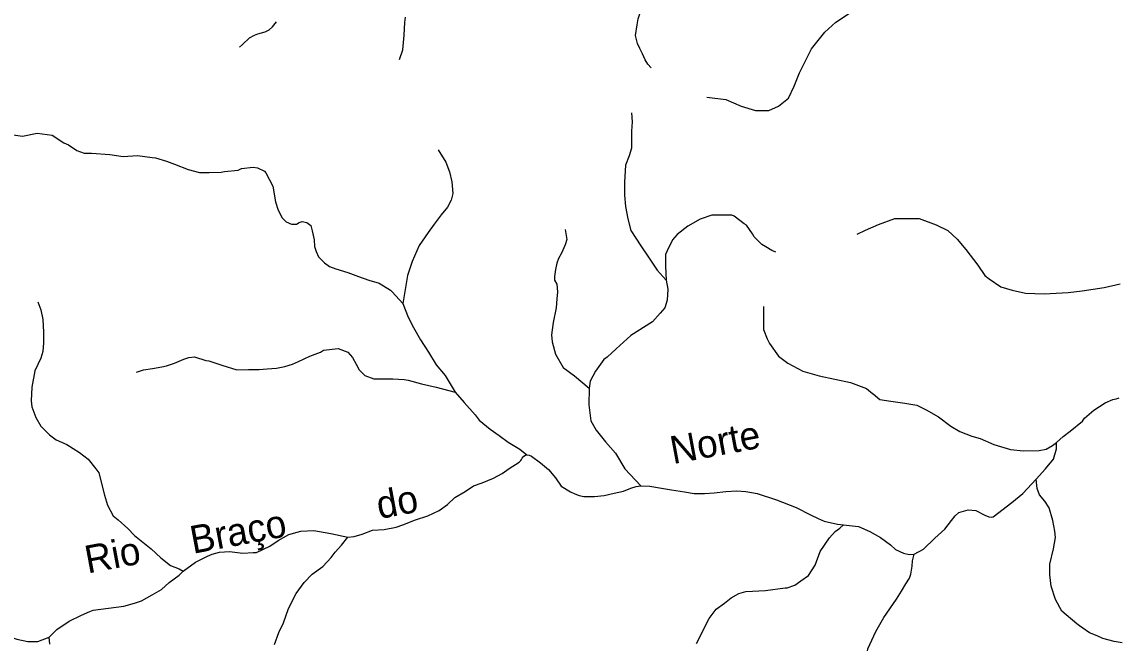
# Model space of a CAD drawing. Extents: x 436.3 to 500.4, y 8231 to 8286.4.
# Drawn here: x 465.65 to 473.55, y 8253.25 to 8257.73 of the extents above; entities that cross this region are included whole.
import ezdxf
from ezdxf.enums import TextEntityAlignment as Align

# ---------------------------------------------------------------- set-up
doc = ezdxf.new("R2010")
doc.units = 0
doc.header["$LTSCALE"] = 0.08
doc.linetypes.add('LONG_DASHED', pattern=[7.5, 6, -1.5])
doc.layers.add('61', color=7, linetype='Continuous')
doc.layers.add('9', color=7, linetype='LONG_DASHED', lineweight=25)

msp = doc.modelspace()

# ---------------------------------------------------------------- linework, layer by layer
at = {"layer": '9'}
for points in [[(470.1875, 8257.4013), (470.1642, 8257.4285), (470.1446, 8257.4597), (470.1251, 8257.5025), (470.1055, 8257.5413), (470.09, 8257.5764), (470.0743, 8257.6348), (470.086, 8257.7126), (470.0937, 8257.7554), (470.1248, 8257.8489), (470.1793, 8257.9541), (470.2804, 8258.0726), (470.335, 8258.1505), (470.3622, 8258.2011), (470.3856, 8258.2751), (470.3939, 8258.3915)], [(470.5903, 8257.1891), (470.7255, 8257.1733), (470.8369, 8257.1257), (470.9403, 8257.0941), (471.0358, 8257.0942), (471.1074, 8257.126), (471.1789, 8257.1818), (471.2186, 8257.2692), (471.2582, 8257.3645), (471.3456, 8257.5393), (471.441, 8257.6585), (471.5204, 8257.73), (471.6397, 8257.8095)], [(467.2197, 8257.5506), (467.2402, 8257.571), (467.2914, 8257.6171), (467.3272, 8257.6375), (467.3511, 8257.6467), (467.3777, 8257.6547), (467.4042, 8257.6625), (467.4333, 8257.6758), (467.4571, 8257.6969), (467.4862, 8257.7339)], [(468.3732, 8257.4622), (468.396, 8257.531), (468.4074, 8257.6378), (468.4112, 8257.7294), (468.415, 8257.7675)], [(470.0459, 8257.0776), (470.0515, 8257.011), (470.046, 8256.9444), (470.0461, 8256.8723), (470.0461, 8256.8224), (470.0295, 8256.7668), (470.0017, 8256.7002), (469.9963, 8256.5781), (469.9964, 8256.4837), (470.0019, 8256.4004), (470.0186, 8256.3116), (470.0409, 8256.2283), (470.1131, 8256.1172), (470.1744, 8256.0285), (470.2302, 8255.9429), (470.2968, 8255.8708)], [(465.5532, 8256.9221), (465.6546, 8256.9093), (465.7593, 8256.9313), (465.8671, 8256.9153), (465.9526, 8256.8614), (465.9844, 8256.8455), (466.0447, 8256.8043), (466.0985, 8256.7851), (466.1524, 8256.785), (466.2824, 8256.7754), (466.3806, 8256.7625), (466.482, 8256.7688), (466.5898, 8256.756), (466.612, 8256.7527), (466.6933, 8256.7296), (466.7504, 8256.7073), (466.8486, 8256.6691), (466.931, 8256.6469), (467.0007, 8256.6468), (467.0863, 8256.6499), (467.1117, 8256.653), (467.2099, 8256.6624), (467.2321, 8256.6751), (467.3176, 8256.6845), (467.3493, 8256.6813), (467.4, 8256.6559), (467.4095, 8256.6432), (467.4602, 8256.5481), (467.4793, 8256.4339), (467.4951, 8256.3833), (467.5236, 8256.323), (467.5553, 8256.2913), (467.5946, 8256.2743), (467.6294, 8256.2742), (467.6484, 8256.2869), (467.6706, 8256.2932), (467.7054, 8256.2869), (467.7339, 8256.2647), (467.7435, 8256.2266), (467.7562, 8256.16), (467.7593, 8256.1124), (467.7721, 8256.0775), (467.7878, 8256.0394), (467.8322, 8255.995), (467.8671, 8255.9696), (467.9146, 8255.9506), (468.0002, 8255.9251), (468.0762, 8255.8965), (468.1522, 8255.8711), (468.2251, 8255.8489), (468.3075, 8255.7982), (468.3202, 8255.7855), (468.3974, 8255.701)], [(468.6513, 8256.8105), (468.7066, 8256.7222), (468.7343, 8256.6504), (468.7509, 8256.5786), (468.7564, 8256.4958), (468.7454, 8256.446), (468.7179, 8256.3963), (468.6737, 8256.341), (468.624, 8256.2747), (468.5798, 8256.2138), (468.5136, 8256.1199), (468.464, 8256.0038), (468.4308, 8255.9042), (468.3974, 8255.701)], [(471.0863, 8256.0721), (471.0585, 8256.0831), (471.0141, 8256.1109), (470.9863, 8256.1275), (470.9307, 8256.1829), (470.9196, 8256.2051), (470.8751, 8256.2661), (470.8585, 8256.2772), (470.7862, 8256.3326), (470.7695, 8256.3382), (470.6474, 8256.338), (470.6249, 8256.3381), (470.5416, 8256.3102), (470.4529, 8256.2601), (470.3747, 8256.1987), (470.3414, 8256.1598), (470.3026, 8256.082), (470.2916, 8256.0542), (470.2916, 8255.9708), (470.2968, 8255.8708)], [(471.6748, 8256.2018), (471.733, 8256.231), (471.8286, 8256.2727), (471.9451, 8256.3143), (472.1199, 8256.3144), (472.2447, 8256.2687), (472.3281, 8256.2272), (472.3947, 8256.1649), (472.4572, 8256.0901), (472.5448, 8255.9778), (472.5949, 8255.9029), (472.6261, 8255.8804), (472.7094, 8255.8222), (472.7928, 8255.7972), (472.8886, 8255.7764), (473.0219, 8255.7723), (473.1967, 8255.7805), (473.2967, 8255.793), (473.455, 8255.8179), (473.5716, 8255.8428)], [(469.5689, 8256.2356), (469.58, 8256.1643), (469.5689, 8256.1254), (469.5412, 8256.0642), (469.519, 8256.0253), (469.5079, 8255.992), (469.4968, 8255.9475), (469.4913, 8255.8975), (469.4913, 8255.8697), (469.508, 8255.8419), (469.5136, 8255.7863), (469.508, 8255.7363), (469.5025, 8255.6695), (469.4804, 8255.5638), (469.4693, 8255.4748), (469.4749, 8255.4248), (469.4972, 8255.3358), (469.5527, 8255.2412), (469.636, 8255.1801), (469.7416, 8255.0906)], [(470.2968, 8255.8708), (470.3084, 8255.8041), (470.3029, 8255.7263), (470.2863, 8255.6706), (470.253, 8255.6317), (470.1974, 8255.5704), (470.042, 8255.4701), (469.9366, 8255.3754), (469.87, 8255.3141), (469.8478, 8255.2974), (469.7867, 8255.2139), (469.7479, 8255.1414), (469.7416, 8255.0906)], [(465.7643, 8255.713), (465.7853, 8255.657), (465.7992, 8255.587), (465.8062, 8255.496), (465.8062, 8255.4191), (465.7992, 8255.3561), (465.7852, 8255.3071), (465.7432, 8255.2161), (465.7222, 8255.0972), (465.7152, 8254.9991), (465.7222, 8254.957), (465.7501, 8254.88), (465.785, 8254.8168), (465.8478, 8254.7537), (465.8967, 8254.7186), (465.9735, 8254.6835), (466.0643, 8254.6273), (466.1271, 8254.5782), (466.183, 8254.508), (466.2039, 8254.4799), (466.2457, 8254.3187), (466.2668, 8254.2468), (466.3087, 8254.1696), (466.3436, 8254.1416), (466.4134, 8254.0784), (466.4623, 8254.0292), (466.5809, 8253.931), (466.6507, 8253.8678), (466.7206, 8253.8116), (466.7832, 8253.7879), (466.8131, 8253.772)], [(468.3974, 8255.701), (468.4355, 8255.6025), (468.4735, 8255.5295), (468.5243, 8255.4406), (468.5813, 8255.3517), (468.6384, 8255.2596), (468.7018, 8255.1834), (468.7747, 8255.0627)], [(470.9989, 8255.6807), (470.999, 8255.5639), (470.999, 8255.5139), (471.0241, 8255.4471), (471.0408, 8255.4138), (471.1076, 8255.322), (471.1743, 8255.272), (471.2828, 8255.2137), (471.3996, 8255.1805), (471.6248, 8255.1307), (471.7416, 8255.0891), (471.7845, 8255.0533), (471.7881, 8255.0497), (471.8382, 8255.0103), (471.917, 8254.996), (472.0173, 8254.9818), (472.1033, 8254.9676), (472.1713, 8254.9353), (472.2609, 8254.8852), (472.3505, 8254.8172), (472.415, 8254.7777), (472.5011, 8254.7456), (472.562, 8254.7277), (472.6588, 8254.6847), (472.7806, 8254.6489), (472.8738, 8254.6382), (472.987, 8254.6408), (473.0372, 8254.6516), (473.0837, 8254.6768), (473.1124, 8254.6997)], [(466.4749, 8255.206), (466.5263, 8255.2232), (466.5905, 8255.2317), (466.6591, 8255.2445), (466.6933, 8255.2531), (466.7491, 8255.2702), (466.8175, 8255.3002), (466.8522, 8255.3129), (466.8947, 8255.3172), (466.9761, 8255.2914), (466.9974, 8255.2871), (467.0917, 8255.257), (467.1991, 8255.2224), (467.2845, 8255.2268), (467.3615, 8255.2267), (467.4173, 8255.231), (467.4857, 8255.2352), (467.5456, 8255.248), (467.6014, 8255.2652), (467.6442, 8255.2823), (467.7255, 8255.3209), (467.8026, 8255.3509), (467.8241, 8255.3639), (467.9311, 8255.3767), (467.9996, 8255.3509), (468.0339, 8255.3122), (468.0596, 8255.2651), (468.0811, 8255.2221), (468.1239, 8255.1835), (468.1881, 8255.1577), (468.2481, 8255.1577), (468.3252, 8255.1577), (468.4065, 8255.1534), (468.4365, 8255.1491), (468.5307, 8255.1234), (468.6377, 8255.0976), (468.7747, 8255.0627)], [(469.7416, 8255.0906), (469.7386, 8254.9696), (469.7534, 8254.8549), (469.7923, 8254.7881), (469.8589, 8254.7047), (469.9312, 8254.6212), (469.9979, 8254.51), (470.1146, 8254.3875)], [(468.7747, 8255.0627), (468.8381, 8254.9865), (468.9184, 8254.8989), (468.9468, 8254.8607), (469.0262, 8254.7941), (469.0927, 8254.7496), (469.1561, 8254.702), (469.2417, 8254.6512), (469.2909, 8254.6106)], [(473.1124, 8254.6997), (473.1589, 8254.7413), (473.209, 8254.7808), (473.2985, 8254.8525), (473.3129, 8254.874), (473.381, 8254.9313), (473.4633, 8254.985), (473.5171, 8255.0101), (473.5422, 8255.0138), (473.5637, 8255.0209)], [(472.9649, 8254.4349), (473.0315, 8254.5081), (473.089, 8254.5794), (473.1113, 8254.6526), (473.1124, 8254.6997)], [(467.9997, 8254.0164), (468.0447, 8254.0212), (468.1047, 8254.0389), (468.1787, 8254.0673), (468.2633, 8254.0708), (468.348, 8254.0886), (468.3973, 8254.1063), (468.489, 8254.1417), (468.5772, 8254.1701), (468.6583, 8254.2091), (468.7182, 8254.2516), (468.7711, 8254.3013), (468.8464, 8254.345), (468.9064, 8254.3876), (468.9698, 8254.4089), (469.0509, 8254.4407), (469.1144, 8254.4762), (469.1643, 8254.5113), (469.2362, 8254.5578), (469.2469, 8254.568), (469.2533, 8254.5766), (469.2587, 8254.5863), (469.2684, 8254.5993), (469.2808, 8254.6079), (469.2909, 8254.6106)], [(469.2909, 8254.6106), (469.3071, 8254.6084), (469.3238, 8254.5998), (469.3907, 8254.5528), (469.4477, 8254.5052), (469.4985, 8254.4448), (469.5398, 8254.3844), (469.6063, 8254.3432), (469.6364, 8254.329), (469.6681, 8254.3163), (469.703, 8254.31), (469.7791, 8254.3101), (469.8488, 8254.3165), (469.9217, 8254.3325), (469.9883, 8254.3485), (470.0421, 8254.3708), (470.0802, 8254.3805), (470.1146, 8254.3875)], [(470.1146, 8254.3875), (470.1785, 8254.3837), (470.2482, 8254.3711), (470.3339, 8254.3586), (470.429, 8254.3428), (470.4987, 8254.3302), (470.5717, 8254.3303), (470.6415, 8254.3367), (470.727, 8254.3464), (470.8064, 8254.3497), (470.8698, 8254.3467), (470.9523, 8254.3308), (471.0918, 8254.2865), (471.233, 8254.2291), (471.3377, 8254.1784), (471.3917, 8254.1498), (471.4361, 8254.1309), (471.5323, 8254.1111), (471.5758, 8254.105)], [(472.0852, 8253.8931), (472.1511, 8253.9305), (472.2336, 8254.0101), (472.3066, 8254.0737), (472.3541, 8254.1374), (472.3795, 8254.1692), (472.408, 8254.1947), (472.4747, 8254.2138), (472.5287, 8254.2075), (472.5954, 8254.1758), (472.6223, 8254.1637), (472.6413, 8254.1606), (472.654, 8254.1638), (472.7904, 8254.2663), (472.8697, 8254.33), (472.9649, 8254.4349)], [(473.5859, 8253.2542), (473.5268, 8253.2633), (473.4451, 8253.286), (473.4041, 8253.3041), (473.3496, 8253.3268), (473.277, 8253.3768), (473.2587, 8253.3904), (473.1497, 8253.4812), (473.1042, 8253.5676), (473.0723, 8253.6631), (473.0632, 8253.7449), (473.0631, 8253.8222), (473.0903, 8253.9314), (473.1038, 8254.0132), (473.0993, 8254.0587), (473.0855, 8254.1359), (473.0582, 8254.2268), (473.0264, 8254.2768), (472.99, 8254.3222), (472.9718, 8254.3676), (472.9649, 8254.4349)], [(466.8131, 8253.772), (466.9026, 8253.837), (466.9873, 8253.8794), (467.0225, 8253.8935), (467.0754, 8253.9078), (467.1474, 8253.9117), (467.2426, 8253.901), (467.3167, 8253.9045), (467.3414, 8253.9045), (467.4366, 8253.9505), (467.4966, 8253.9931), (467.5741, 8254.0355), (467.6341, 8254.0533), (467.6623, 8254.0603), (467.754, 8254.0639), (467.8775, 8254.0426), (467.9997, 8254.0164)], [(470.5153, 8253.2498), (470.6071, 8253.4302), (470.6557, 8253.4977), (470.7167, 8253.5398), (470.7645, 8253.5786), (470.8204, 8253.6103), (470.8696, 8253.6251), (471.0123, 8253.6303), (471.155, 8253.6503), (471.1698, 8253.6503), (471.224, 8253.671), (471.2683, 8253.7007), (471.3225, 8253.7403), (471.3715, 8253.8144), (471.4059, 8253.9132), (471.4748, 8254.012), (471.5141, 8254.0565), (471.5485, 8254.0812), (471.5758, 8254.105)], [(471.5758, 8254.105), (471.6837, 8254.093), (471.7662, 8254.0581), (471.8424, 8254.0137), (471.9131, 8253.9619), (471.9512, 8253.927), (472.0083, 8253.9016), (472.0496, 8253.8921), (472.0852, 8253.8931)], [(467.4712, 8253.2421), (467.5022, 8253.329), (467.5367, 8253.3984), (467.5714, 8253.5026), (467.6265, 8253.6103), (467.6853, 8253.6901), (467.7441, 8253.7491), (467.82, 8253.8046), (467.8788, 8253.8705), (467.9098, 8253.9088), (467.9548, 8253.9574), (467.9997, 8254.0164)], [(471.8177, 8252.3479), (471.8009, 8252.5572), (471.7842, 8252.6828), (471.7423, 8252.8418), (471.7256, 8252.9087), (471.7256, 8253.0259), (471.7505, 8253.21), (471.8088, 8253.3356), (471.8672, 8253.4361), (471.9565, 8253.5683), (471.9942, 8253.6267), (472.024, 8253.6787), (472.0508, 8253.7213), (472.0601, 8253.7496), (472.0711, 8253.8064), (472.0726, 8253.8457), (472.0852, 8253.8931)], [(465.846, 8253.2944), (465.9025, 8253.3511), (465.9907, 8253.4114), (466.079, 8253.454), (466.139, 8253.4788), (466.1637, 8253.4894), (466.2731, 8253.5035), (466.3839, 8253.5181), (466.4616, 8253.5393), (466.511, 8253.5571), (466.5886, 8253.5996), (466.6557, 8253.6385), (466.7121, 8253.6881), (466.7827, 8253.7413), (466.8131, 8253.772)], [(465.5283, 8253.3087), (465.6131, 8253.2803), (465.6913, 8253.2631), (465.7649, 8253.2625), (465.846, 8253.2944)], [(465.8512, 8253.2435), (465.846, 8253.2944)]]:
    msp.add_lwpolyline(points, dxfattribs=at)

# ---------------------------------------------------------------- texts
at = {"layer": '61'}
msp.add_text('Rio     Braço         do                         Norte', height=0.2, rotation=10.589, dxfattribs=at).set_placement((468.5559, 8254.2083), align=Align.CENTER)

doc.saveas('drawing.dxf')
